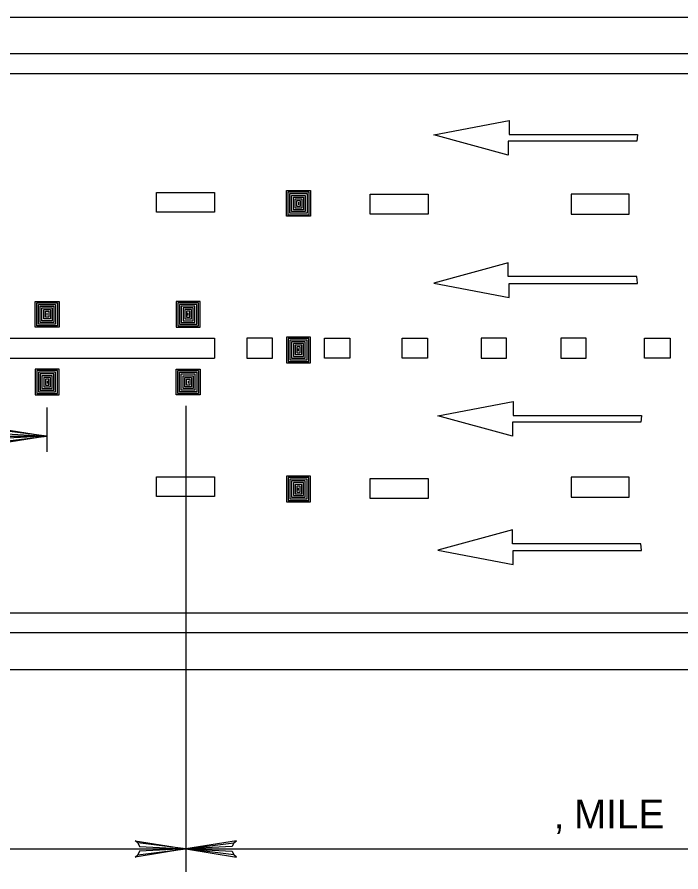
# Model space of a CAD drawing. Extents: x 639362 to 641108, y 298458 to 299646.
# Drawn here: x 639652.3 to 639721.2, y 299173.9 to 299262.6 of the extents above; entities that cross this region are included whole.
import ezdxf

# ---------------------------------------------------------------- set-up
doc = ezdxf.new("R2010")
doc.units = 0
doc.layers.add('2', color=7, linetype='Continuous')

msp = doc.modelspace()

# ---------------------------------------------------------------- linework, layer by layer
at = {"layer": '2'}
for p, q in [((639583.095, 299262.592), (639789.679, 299262.592)), ((639583.09, 299258.806), (639789.679, 299258.806)), ((639583.088, 299256.742), (639789.679, 299256.742)), ((639695.526, 299250.389), (639703.33, 299251.865)), ((639703.33, 299251.865), (639703.33, 299250.42)), ((639703.25, 299248.272), (639695.526, 299250.389)), ((639716.576, 299249.716), (639703.25, 299249.716)), ((639703.25, 299249.716), (639703.25, 299248.272)), ((639703.33, 299250.42), (639716.657, 299250.42)), ((639716.657, 299250.389), (639716.576, 299249.716)), ((639716.657, 299250.42), (639716.657, 299250.389)), ((639666.725, 299242.341), (639666.725, 299244.405)), ((639666.725, 299244.405), (639672.738, 299244.405)), ((639672.738, 299244.405), (639672.738, 299242.341)), ((639680.219, 299244.587), (639682.715, 299244.587)), ((639680.219, 299241.932), (639680.219, 299244.587)), ((639680.403, 299244.454), (639682.532, 299244.454)), ((639680.403, 299242.059), (639680.403, 299244.454)), ((639680.583, 299244.278), (639682.357, 299244.278)), ((639680.583, 299242.239), (639680.583, 299244.278)), ((639682.357, 299244.278), (639682.357, 299242.239)), ((639682.532, 299244.454), (639682.532, 299242.059)), ((639682.715, 299244.587), (639682.715, 299241.932)), ((639680.76, 299244.1), (639682.177, 299244.1)), ((639680.76, 299242.413), (639680.76, 299244.1)), ((639680.936, 299243.923), (639682, 299243.923)), ((639680.936, 299242.591), (639680.936, 299243.923)), ((639681.113, 299242.768), (639681.113, 299243.744)), ((639681.113, 299243.744), (639681.825, 299243.744)), ((639681.292, 299243.567), (639681.648, 299243.567)), ((639681.292, 299242.947), (639681.292, 299243.567)), ((639681.468, 299243.39), (639681.468, 299243.124)), ((639681.648, 299243.567), (639681.648, 299242.947)), ((639681.825, 299243.744), (639681.825, 299242.768)), ((639682, 299243.923), (639682, 299242.591)), ((639682.177, 299244.1), (639682.177, 299242.413)), ((639688.913, 299242.153), (639688.913, 299244.217)), ((639688.913, 299244.217), (639694.927, 299244.217)), ((639694.927, 299244.217), (639694.927, 299242.153)), ((639715.797, 299244.217), (639709.784, 299244.217)), ((639709.784, 299244.217), (639709.784, 299242.153)), ((639715.797, 299242.153), (639715.797, 299244.217)), ((639682, 299242.591), (639680.936, 299242.591)), ((639681.825, 299242.768), (639681.113, 299242.768)), ((639681.648, 299242.947), (639681.292, 299242.947)), ((639672.738, 299242.341), (639666.725, 299242.341)), ((639682.715, 299241.932), (639680.219, 299241.932)), ((639682.532, 299242.059), (639680.403, 299242.059)), ((639682.357, 299242.239), (639680.583, 299242.239)), ((639682.177, 299242.413), (639680.76, 299242.413)), ((639694.927, 299242.153), (639688.913, 299242.153)), ((639709.784, 299242.153), (639715.797, 299242.153)), ((639703.25, 299237.107), (639695.526, 299234.99)), ((639703.25, 299235.663), (639703.25, 299237.107)), ((639716.576, 299235.663), (639703.25, 299235.663)), ((639716.657, 299234.99), (639716.576, 299235.663)), ((639695.526, 299234.99), (639703.33, 299233.514)), ((639703.33, 299233.514), (639703.33, 299234.958)), ((639703.33, 299234.958), (639716.657, 299234.958)), ((639716.657, 299234.958), (639716.657, 299234.99)), ((639654.132, 299230.433), (639654.132, 299233.087)), ((639654.132, 299233.087), (639656.628, 299233.087)), ((639654.314, 299230.566), (639654.314, 299232.961)), ((639654.314, 299232.961), (639656.443, 299232.961)), ((639654.49, 299230.742), (639654.49, 299232.781)), ((639654.49, 299232.781), (639656.263, 299232.781)), ((639656.263, 299232.781), (639656.263, 299230.742)), ((639656.443, 299232.961), (639656.443, 299230.566)), ((639656.628, 299233.087), (639656.628, 299230.433)), ((639671.263, 299233.087), (639668.767, 299233.087)), ((639668.767, 299233.087), (639668.767, 299230.433)), ((639671.08, 299232.961), (639668.951, 299232.961)), ((639668.951, 299232.961), (639668.951, 299230.566)), ((639670.905, 299232.781), (639669.131, 299232.781)), ((639669.131, 299232.781), (639669.131, 299230.742)), ((639670.905, 299230.742), (639670.905, 299232.781)), ((639671.08, 299230.566), (639671.08, 299232.961)), ((639671.263, 299230.433), (639671.263, 299233.087)), ((639654.669, 299230.92), (639654.669, 299232.607)), ((639654.669, 299232.607), (639656.086, 299232.607)), ((639654.846, 299231.097), (639654.846, 299232.428)), ((639654.846, 299232.428), (639655.911, 299232.428)), ((639655.022, 299231.275), (639655.022, 299232.251)), ((639655.022, 299232.251), (639655.734, 299232.251)), ((639655.199, 299231.452), (639655.199, 299232.073)), ((639655.199, 299232.073), (639655.554, 299232.073)), ((639655.379, 299231.629), (639655.379, 299231.896)), ((639655.554, 299232.073), (639655.554, 299231.452)), ((639655.734, 299232.251), (639655.734, 299231.275)), ((639655.911, 299232.428), (639655.911, 299231.097)), ((639656.086, 299232.607), (639656.086, 299230.92)), ((639670.725, 299232.607), (639669.308, 299232.607)), ((639669.308, 299232.607), (639669.308, 299230.92)), ((639670.548, 299232.428), (639669.484, 299232.428)), ((639669.484, 299232.428), (639669.484, 299231.097)), ((639670.373, 299232.251), (639669.661, 299232.251)), ((639669.661, 299232.251), (639669.661, 299231.275)), ((639670.196, 299232.073), (639669.84, 299232.073)), ((639669.84, 299232.073), (639669.84, 299231.452)), ((639670.016, 299231.629), (639670.016, 299231.896)), ((639670.196, 299231.452), (639670.196, 299232.073)), ((639670.373, 299231.275), (639670.373, 299232.251)), ((639670.548, 299231.097), (639670.548, 299232.428)), ((639670.725, 299230.92), (639670.725, 299232.607)), ((639655.911, 299231.097), (639654.846, 299231.097)), ((639655.734, 299231.275), (639655.022, 299231.275)), ((639655.554, 299231.452), (639655.199, 299231.452)), ((639669.484, 299231.097), (639670.548, 299231.097)), ((639669.661, 299231.275), (639670.373, 299231.275)), ((639669.84, 299231.452), (639670.196, 299231.452)), ((639656.628, 299230.433), (639654.132, 299230.433)), ((639656.443, 299230.566), (639654.314, 299230.566)), ((639656.263, 299230.742), (639654.49, 299230.742)), ((639656.086, 299230.92), (639654.669, 299230.92)), ((639668.767, 299230.433), (639671.263, 299230.433)), ((639668.951, 299230.566), (639671.08, 299230.566)), ((639669.131, 299230.742), (639670.905, 299230.742)), ((639669.308, 299230.92), (639670.725, 299230.92)), ((639583.053, 299229.278), (639672.738, 299229.278)), ((639672.738, 299229.278), (639672.738, 299227.209)), ((639678.756, 299229.276), (639676.121, 299229.276)), ((639676.121, 299229.276), (639676.121, 299227.211)), ((639678.756, 299227.211), (639678.756, 299229.276)), ((639682.715, 299229.385), (639680.219, 299229.385)), ((639680.219, 299229.385), (639680.219, 299226.73)), ((639682.532, 299229.258), (639680.403, 299229.258)), ((639680.403, 299229.258), (639680.403, 299226.864)), ((639682.532, 299226.864), (639682.532, 299229.258)), ((639682.715, 299226.73), (639682.715, 299229.385)), ((639684.177, 299227.211), (639684.177, 299229.276)), ((639684.177, 299229.276), (639686.812, 299229.276)), ((639686.812, 299229.276), (639686.812, 299227.211)), ((639692.232, 299227.211), (639692.232, 299229.276)), ((639692.232, 299229.276), (639694.867, 299229.276)), ((639694.867, 299229.276), (639694.867, 299227.211)), ((639703.073, 299229.276), (639700.438, 299229.276)), ((639700.438, 299229.276), (639700.438, 299227.211)), ((639703.073, 299227.211), (639703.073, 299229.276)), ((639711.335, 299229.276), (639708.7, 299229.276)), ((639708.7, 299229.276), (639708.7, 299227.211)), ((639711.335, 299227.211), (639711.335, 299229.276)), ((639717.404, 299227.211), (639717.404, 299229.276)), ((639717.404, 299229.276), (639720.039, 299229.276)), ((639720.039, 299229.276), (639720.039, 299227.211)), ((639682.357, 299229.079), (639680.583, 299229.079)), ((639680.583, 299229.079), (639680.583, 299227.039)), ((639682.177, 299228.904), (639680.76, 299228.904)), ((639680.76, 299228.904), (639680.76, 299227.218)), ((639682, 299228.726), (639680.936, 299228.726)), ((639680.936, 299228.726), (639680.936, 299227.395)), ((639681.825, 299228.549), (639681.113, 299228.549)), ((639681.113, 299228.549), (639681.113, 299227.573)), ((639681.648, 299228.371), (639681.292, 299228.371)), ((639681.292, 299228.371), (639681.292, 299227.75)), ((639681.648, 299227.75), (639681.648, 299228.371)), ((639681.825, 299227.573), (639681.825, 299228.549)), ((639682, 299227.395), (639682, 299228.726)), ((639682.177, 299227.218), (639682.177, 299228.904)), ((639682.357, 299227.039), (639682.357, 299229.079)), ((639681.113, 299227.573), (639681.825, 299227.573)), ((639681.292, 299227.75), (639681.648, 299227.75)), ((639681.468, 299227.927), (639681.468, 299228.194)), ((639583.053, 299227.209), (639672.738, 299227.209)), ((639676.121, 299227.211), (639678.756, 299227.211)), ((639680.219, 299226.73), (639682.715, 299226.73)), ((639680.403, 299226.864), (639682.532, 299226.864)), ((639680.583, 299227.039), (639682.357, 299227.039)), ((639680.76, 299227.218), (639682.177, 299227.218)), ((639680.936, 299227.395), (639682, 299227.395)), ((639686.812, 299227.211), (639684.177, 299227.211)), ((639694.867, 299227.211), (639692.232, 299227.211)), ((639700.438, 299227.211), (639703.073, 299227.211)), ((639708.7, 299227.211), (639711.335, 299227.211)), ((639720.039, 299227.211), (639717.404, 299227.211)), ((639656.628, 299226.054), (639654.132, 299226.054)), ((639654.132, 299226.054), (639654.132, 299223.4)), ((639656.443, 299225.921), (639654.314, 299225.921)), ((639654.314, 299225.921), (639654.314, 299223.527)), ((639656.263, 299225.745), (639654.49, 299225.745)), ((639654.49, 299225.745), (639654.49, 299223.706)), ((639656.263, 299223.706), (639656.263, 299225.745)), ((639656.443, 299223.527), (639656.443, 299225.921)), ((639656.628, 299223.4), (639656.628, 299226.054)), ((639668.767, 299226.054), (639671.263, 299226.054)), ((639668.767, 299223.4), (639668.767, 299226.054)), ((639668.951, 299225.921), (639671.08, 299225.921)), ((639668.951, 299223.527), (639668.951, 299225.921)), ((639669.131, 299225.745), (639670.905, 299225.745)), ((639669.131, 299223.706), (639669.131, 299225.745)), ((639670.905, 299225.745), (639670.905, 299223.706)), ((639671.08, 299225.921), (639671.08, 299223.527)), ((639671.263, 299226.054), (639671.263, 299223.4)), ((639656.086, 299225.567), (639654.669, 299225.567)), ((639654.669, 299225.567), (639654.669, 299223.881)), ((639655.911, 299225.39), (639654.846, 299225.39)), ((639654.846, 299225.39), (639654.846, 299224.059)), ((639655.022, 299225.212), (639655.022, 299224.236)), ((639655.734, 299225.212), (639655.022, 299225.212)), ((639655.554, 299225.035), (639655.199, 299225.035)), ((639655.199, 299225.035), (639655.199, 299224.414)), ((639655.379, 299224.858), (639655.379, 299224.591)), ((639655.554, 299224.414), (639655.554, 299225.035)), ((639655.734, 299224.236), (639655.734, 299225.212)), ((639655.911, 299224.059), (639655.911, 299225.39)), ((639656.086, 299223.881), (639656.086, 299225.567)), ((639669.308, 299225.567), (639670.725, 299225.567)), ((639669.308, 299223.881), (639669.308, 299225.567)), ((639669.484, 299225.39), (639670.548, 299225.39)), ((639669.484, 299224.059), (639669.484, 299225.39)), ((639669.661, 299224.236), (639669.661, 299225.212)), ((639669.661, 299225.212), (639670.373, 299225.212)), ((639669.84, 299225.035), (639670.196, 299225.035)), ((639669.84, 299224.414), (639669.84, 299225.035)), ((639670.016, 299224.858), (639670.016, 299224.591)), ((639670.196, 299225.035), (639670.196, 299224.414)), ((639670.373, 299225.212), (639670.373, 299224.236)), ((639670.548, 299225.39), (639670.548, 299224.059)), ((639670.725, 299225.567), (639670.725, 299223.881)), ((639654.669, 299223.881), (639656.086, 299223.881)), ((639654.846, 299224.059), (639655.911, 299224.059)), ((639655.022, 299224.236), (639655.734, 299224.236)), ((639655.199, 299224.414), (639655.554, 299224.414)), ((639670.725, 299223.881), (639669.308, 299223.881)), ((639670.548, 299224.059), (639669.484, 299224.059)), ((639670.373, 299224.236), (639669.661, 299224.236)), ((639670.196, 299224.414), (639669.84, 299224.414)), ((639654.132, 299223.4), (639656.628, 299223.4)), ((639654.314, 299223.527), (639656.443, 299223.527)), ((639654.49, 299223.706), (639656.263, 299223.706)), ((639671.263, 299223.4), (639668.767, 299223.4)), ((639671.08, 299223.527), (639668.951, 299223.527)), ((639670.905, 299223.706), (639669.131, 299223.706)), ((639655.337, 299222.104), (639655.337, 299217.479)), ((639669.771, 299222.253), (639669.771, 299173.909)), ((639695.951, 299221.233), (639703.755, 299222.709)), ((639703.755, 299222.709), (639703.755, 299221.265)), ((639703.675, 299219.116), (639695.951, 299221.233)), ((639703.755, 299221.265), (639717.081, 299221.265)), ((639717.081, 299221.233), (639717.001, 299220.56)), ((639717.081, 299221.265), (639717.081, 299221.233)), ((639717.001, 299220.56), (639703.675, 299220.56)), ((639703.675, 299220.56), (639703.675, 299219.116)), ((639640.264, 299219.116), (639655.337, 299219.116)), ((639666.725, 299212.848), (639666.725, 299214.913)), ((639666.725, 299214.913), (639672.738, 299214.913)), ((639672.738, 299214.913), (639672.738, 299212.848)), ((639682.715, 299214.951), (639680.219, 299214.951)), ((639680.219, 299214.951), (639680.219, 299212.297)), ((639682.532, 299214.825), (639680.403, 299214.825)), ((639680.403, 299214.825), (639680.403, 299212.43)), ((639682.357, 299214.645), (639680.583, 299214.645)), ((639680.583, 299214.645), (639680.583, 299212.606)), ((639682.177, 299214.471), (639680.76, 299214.471)), ((639680.76, 299214.471), (639680.76, 299212.784)), ((639682, 299214.292), (639680.936, 299214.292)), ((639680.936, 299214.292), (639680.936, 299212.961)), ((639681.825, 299214.115), (639681.113, 299214.115)), ((639681.113, 299214.115), (639681.113, 299213.139)), ((639681.825, 299213.139), (639681.825, 299214.115)), ((639682, 299212.961), (639682, 299214.292)), ((639682.177, 299212.784), (639682.177, 299214.471)), ((639682.357, 299212.606), (639682.357, 299214.645)), ((639682.532, 299212.43), (639682.532, 299214.825)), ((639682.715, 299212.297), (639682.715, 299214.951)), ((639688.913, 299212.661), (639688.913, 299214.725)), ((639688.913, 299214.725), (639694.927, 299214.725)), ((639694.927, 299214.725), (639694.927, 299212.661)), ((639715.797, 299214.846), (639709.784, 299214.846)), ((639709.784, 299214.846), (639709.784, 299212.782)), ((639715.797, 299212.782), (639715.797, 299214.846)), ((639681.648, 299213.937), (639681.292, 299213.937)), ((639681.292, 299213.937), (639681.292, 299213.316)), ((639681.292, 299213.316), (639681.648, 299213.316)), ((639681.468, 299213.493), (639681.468, 299213.76)), ((639681.648, 299213.316), (639681.648, 299213.937)), ((639672.738, 299212.848), (639666.725, 299212.848)), ((639680.403, 299212.43), (639682.532, 299212.43)), ((639680.583, 299212.606), (639682.357, 299212.606)), ((639680.76, 299212.784), (639682.177, 299212.784)), ((639680.936, 299212.961), (639682, 299212.961)), ((639681.113, 299213.139), (639681.825, 299213.139)), ((639694.927, 299212.661), (639688.913, 299212.661)), ((639709.784, 299212.782), (639715.797, 299212.782)), ((639680.219, 299212.297), (639682.715, 299212.297)), ((639703.675, 299209.406), (639695.951, 299207.289)), ((639703.675, 299207.962), (639703.675, 299209.406)), ((639717.001, 299207.962), (639703.675, 299207.962)), ((639717.081, 299207.289), (639717.001, 299207.962)), ((639695.951, 299207.289), (639703.755, 299205.813)), ((639703.755, 299205.813), (639703.755, 299207.257)), ((639703.755, 299207.257), (639717.081, 299207.257)), ((639717.081, 299207.257), (639717.081, 299207.289)), ((639583.095, 299200.773), (639789.679, 299200.773)), ((639789.679, 299198.709), (639583.098, 299198.709)), ((639583.095, 299194.923), (639789.679, 299194.923)), ((639588.146, 299176.289), (639669.771, 299176.289)), ((639669.771, 299176.289), (639768.267, 299176.289))]:
    msp.add_line(p, q, dxfattribs=at)
for points in [[(639650.342, 299219.743), (639650.528, 299219.382), (639655.337, 299219.116), (639650.342, 299219.743), (639650.086, 299219.962), (639655.337, 299219.116), (639650.532, 299218.879), (639650.357, 299218.521), (639655.337, 299219.116), (639650.086, 299218.282), (639650.357, 299218.521)], [(639664.777, 299176.916), (639664.963, 299176.555), (639669.771, 299176.289), (639664.777, 299176.916), (639664.521, 299177.135), (639669.771, 299176.289), (639664.967, 299176.052), (639664.791, 299175.694), (639669.771, 299176.289), (639664.521, 299175.455), (639664.791, 299175.694)], [(639674.766, 299176.916), (639674.58, 299176.555), (639669.771, 299176.289), (639674.766, 299176.916), (639675.022, 299177.135), (639669.771, 299176.289), (639674.576, 299176.052), (639674.752, 299175.694), (639669.771, 299176.289), (639675.022, 299175.455), (639674.752, 299175.694)]]:
    msp.add_lwpolyline(points, dxfattribs=at)

# ---------------------------------------------------------------- texts
msp.add_text('‚ MILE', height=3, dxfattribs=at).set_placement((639708.065, 299178.415))

doc.saveas('drawing.dxf')
